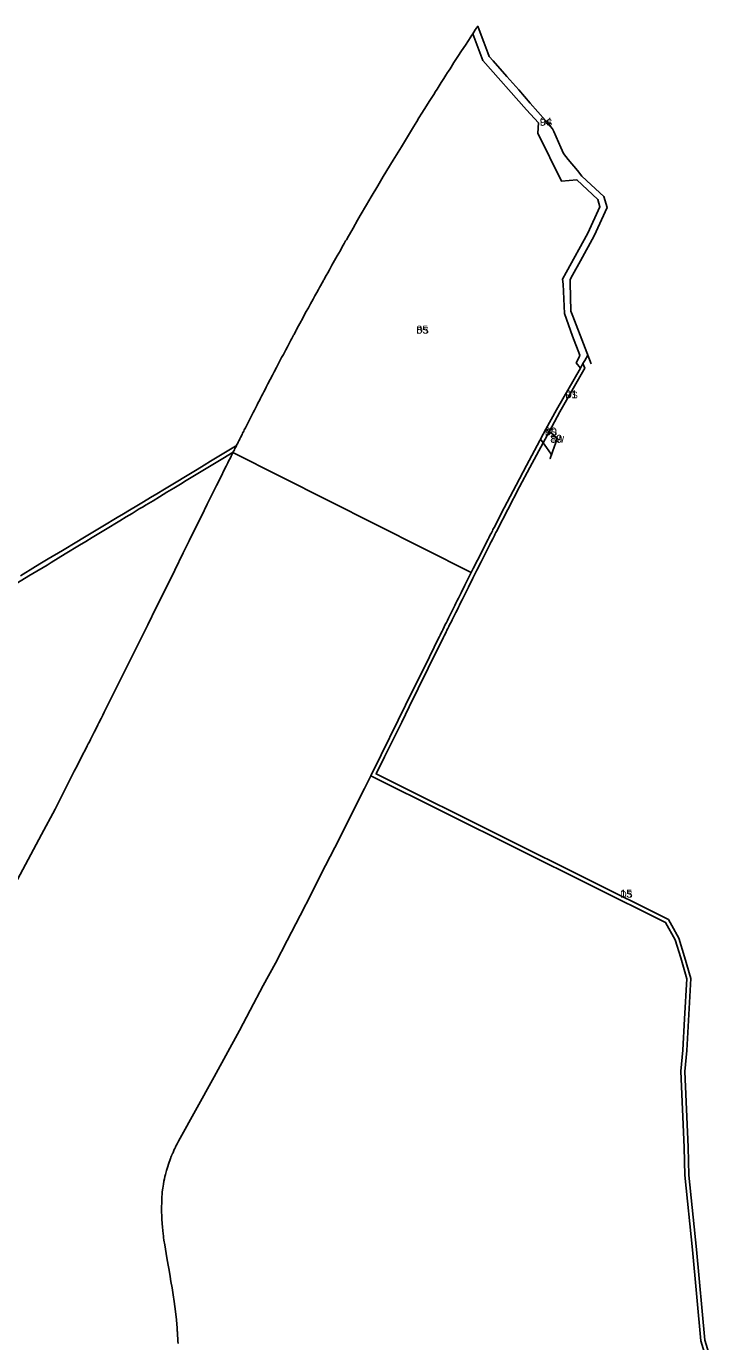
# Model space of a CAD drawing. Extents: x -537034 to -534353, y -1176562 to -1173176.
# Drawn here: x -536087 to -535575, y -1174424 to -1173438 of the extents above; entities that cross this region are included whole.
import ezdxf

# ---------------------------------------------------------------- set-up
doc = ezdxf.new("R2010")
doc.units = 0
for name, color, linetype in [('90320013', 7, 'Continuous'), ('90320023', 7, 'Continuous'), ('90390023', 7, 'Continuous'), ('ID_navrh', 7, 'Continuous')]:
    doc.layers.add(name, color=color, linetype=linetype)

msp = doc.modelspace()

# ---------------------------------------------------------------- linework, layer by layer
at = {"layer": '90320013'}
msp.add_lwpolyline([(-536091.47, -1173850.03), (-536080.14, -1173843.24), (-536075.51, -1173840.47), (-536070.52, -1173837.47), (-536059.98, -1173831.16), (-536049.21, -1173824.7), (-536044.51, -1173821.88), (-536039.74, -1173819.02), (-536029.56, -1173812.91), (-536018.83, -1173806.47), (-536014.02, -1173803.59), (-536009.62, -1173800.95), (-536004.19, -1173797.69), (-536001.59, -1173796.13), (-535999.07, -1173794.61), (-535993.92, -1173791.49), (-535989.09, -1173788.57), (-535983.49, -1173785.18), (-535978.45, -1173782.13), (-535973.46, -1173779.11), (-535968.96, -1173776.39), (-535958.98, -1173770.35), (-535953.57, -1173767.08), (-535948.96, -1173764.29), (-535930.06, -1173752.86), (-535929.43, -1173752.48), (-535929.5, -1173752.61), (-535929.75, -1173753.12), (-535930.17, -1173753.94), (-535930.58, -1173754.76), (-535930.99, -1173755.58), (-535931.4, -1173756.39), (-535931.81, -1173757.21), (-535931.97, -1173757.52), (-535939.75, -1173762.23), (-535960.88, -1173775.01), (-535967.03, -1173778.73), (-535971.51, -1173781.44), (-535976.5, -1173784.46), (-535981.54, -1173787.5), (-535987.18, -1173790.91), (-535991.99, -1173793.82), (-535997.13, -1173796.93), (-536000.01, -1173798.67), (-536002.27, -1173800.04), (-536007.72, -1173803.35), (-536012.05, -1173805.98), (-536016.81, -1173808.87), (-536027.51, -1173815.37), (-536037.66, -1173821.53), (-536042.37, -1173824.39), (-536047.04, -1173827.23), (-536057.75, -1173833.73), (-536068.28, -1173840.12), (-536071.44, -1173842.04), (-536082.06, -1173848.49), (-536085, -1173850.27), (-536124.97, -1173874.53)], dxfattribs=at)
at = {"layer": '90320023'}
for points in [[(-535663.42, -1173691.33), (-535666.09, -1173684.66), (-535668.4, -1173688.75), (-535669.68, -1173691), (-535671.6, -1173694.36), (-535674.68, -1173690.42), (-535672.65, -1173686.12), (-535672.1, -1173684.83), (-535677.54, -1173670.61), (-535683.41, -1173653.53), (-535684.54, -1173631.55), (-535685.07, -1173627.77), (-535682.21, -1173622.82), (-535666.13, -1173593.26), (-535657.03, -1173573.52), (-535658.57, -1173568.09), (-535674.26, -1173553.24), (-535685.71, -1173554.4), (-535703.6, -1173518.27), (-535703.03, -1173510.68), (-535711.9, -1173500.73), (-535744.67, -1173463.76), (-535752.34, -1173443.92), (-535751.46, -1173442.6), (-535750.38, -1173440.96), (-535749.69, -1173439.9), (-535749.4, -1173439.46), (-535749.18, -1173439.12), (-535749.05, -1173438.92), (-535748.57, -1173438.22), (-535746.8, -1173442.83), (-535744, -1173450.12), (-535740.92, -1173458.17), (-535739.9, -1173460.82), (-535737.04, -1173464.08), (-535726.71, -1173475.86), (-535717.86, -1173485.95), (-535709.19, -1173495.84), (-535697.78, -1173508.85), (-535692.41, -1173514.97), (-535691.44, -1173517.18), (-535686.26, -1173529.03), (-535684.28, -1173533.55), (-535680.66, -1173537.97), (-535673.84, -1173546.31), (-535670.41, -1173550.5), (-535663.43, -1173557.09), (-535654.08, -1173565.9), (-535651.65, -1173574.09), (-535661.19, -1173595.23), (-535671.63, -1173614.14), (-535677.56, -1173624.89), (-535679.29, -1173628.03), (-535679.23, -1173630.64), (-535678.7, -1173651.88), (-535677.33, -1173655.42), (-535668, -1173679.5)], [(-535932.12, -1173757.82), (-535931.97, -1173757.52), (-535931.81, -1173757.21), (-535931.4, -1173756.39), (-535930.99, -1173755.58), (-535930.58, -1173754.76), (-535930.17, -1173753.94), (-535929.75, -1173753.12), (-535929.5, -1173752.61), (-535929.43, -1173752.48), (-535929.34, -1173752.3), (-535928.93, -1173751.48), (-535928.52, -1173750.66), (-535928.1, -1173749.84), (-535927.69, -1173749.02), (-535927.28, -1173748.2), (-535926.87, -1173747.39), (-535926.45, -1173746.57), (-535926.04, -1173745.75), (-535925.62, -1173744.93), (-535925.21, -1173744.11), (-535924.8, -1173743.29), (-535924.38, -1173742.47), (-535923.97, -1173741.65), (-535923.55, -1173740.83), (-535923.14, -1173740.01), (-535922.72, -1173739.19), (-535921.47, -1173736.73), (-535920.64, -1173735.09), (-535919.39, -1173732.63), (-535918.13, -1173730.16), (-535916.88, -1173727.7), (-535916.04, -1173726.06), (-535915.2, -1173724.42), (-535913.94, -1173721.96), (-535913.1, -1173720.31), (-535912.25, -1173718.67), (-535911.41, -1173717.03), (-535910.56, -1173715.38), (-535909.72, -1173713.74), (-535908.87, -1173712.1), (-535908.02, -1173710.45), (-535907.17, -1173708.81), (-535905.89, -1173706.34), (-535904.19, -1173703.06), (-535902.48, -1173699.77), (-535901.19, -1173697.3), (-535899.47, -1173694.01), (-535898.61, -1173692.37), (-535897.31, -1173689.9), (-535895.58, -1173686.61), (-535894.28, -1173684.14), (-535892.54, -1173680.85), (-535891.24, -1173678.38), (-535889.92, -1173675.92), (-535888.62, -1173673.46), (-535888.61, -1173673.44), (-535888.6, -1173673.43), (-535888.59, -1173673.41), (-535888.59, -1173673.4), (-535888.58, -1173673.4), (-535888.58, -1173673.39), (-535888.58, -1173673.38), (-535888.57, -1173673.37), (-535888.56, -1173673.35), (-535888.56, -1173673.34), (-535888.55, -1173673.33), (-535888.16, -1173672.6), (-535887.91, -1173672.13), (-535887.71, -1173671.75), (-535887.43, -1173671.24), (-535887.21, -1173670.83), (-535887.04, -1173670.5), (-535886.84, -1173670.13), (-535886.68, -1173669.83), (-535886.46, -1173669.43), (-535886.31, -1173669.14), (-535885.72, -1173668.05), (-535885.31, -1173667.27), (-535884.96, -1173666.61), (-535884.64, -1173666.01), (-535884.21, -1173665.24), (-535883.86, -1173664.58), (-535881.86, -1173660.91), (-535879.78, -1173656.88), (-535877.58, -1173652.84), (-535875.5, -1173649.17), (-535874.03, -1173646.36), (-535872.01, -1173642.75), (-535870.7, -1173640.37), (-535869.29, -1173637.83), (-535868.07, -1173635.6), (-535867.21, -1173634.07), (-535866.5, -1173632.73), (-535865.29, -1173630.57), (-535864.82, -1173629.72), (-535864.19, -1173628.6), (-535863.82, -1173627.94), (-535863.5, -1173627.33), (-535862.2, -1173625.07), (-535861.04, -1173622.93), (-535859.76, -1173620.67), (-535857.86, -1173617.18), (-535855.84, -1173613.7), (-535854.01, -1173610.34), (-535851.56, -1173606.18), (-535850.1, -1173603.55), (-535848.69, -1173601.04), (-535847.65, -1173599.15), (-535847.04, -1173598.17), (-535845.5, -1173595.47), (-535844.79, -1173594.23), (-535842.03, -1173589.46), (-535838.73, -1173583.65), (-535836.59, -1173579.98), (-535832.07, -1173572.1), (-535828.4, -1173565.98), (-535823.51, -1173557.91), (-535819.48, -1173550.82), (-535812.02, -1173538.6), (-535805.78, -1173528.45), (-535796.72, -1173513.55), (-535795.59, -1173511.7), (-535794.26, -1173509.57), (-535792.64, -1173506.93), (-535790.41, -1173503.44), (-535788.7, -1173500.63), (-535787.04, -1173497.94), (-535784.97, -1173494.7), (-535783.04, -1173491.61), (-535781.54, -1173489.23), (-535780.2, -1173487.12), (-535779.1, -1173485.35), (-535775.95, -1173480.36), (-535773.9, -1173477.22), (-535772.4, -1173474.86), (-535771.12, -1173472.81), (-535770.58, -1173471.97), (-535769.29, -1173469.99), (-535768.51, -1173468.76), (-535767.41, -1173467.11), (-535766.37, -1173465.46), (-535763.47, -1173460.97), (-535760.66, -1173456.57), (-535757.85, -1173452.35), (-535755.58, -1173448.83), (-535753.05, -1173444.98), (-535752.34, -1173443.92), (-535744.67, -1173463.76), (-535711.9, -1173500.73), (-535703.03, -1173510.68), (-535703.6, -1173518.27), (-535685.71, -1173554.4), (-535674.26, -1173553.24), (-535658.57, -1173568.09), (-535657.03, -1173573.52), (-535666.13, -1173593.26), (-535682.21, -1173622.82), (-535685.07, -1173627.77), (-535684.54, -1173631.55), (-535683.41, -1173653.53), (-535677.54, -1173670.61), (-535672.1, -1173684.83), (-535672.65, -1173686.12), (-535674.68, -1173690.42), (-535671.6, -1173694.36), (-535689.54, -1173725.83), (-535697.41, -1173740.24), (-535701.53, -1173747.78), (-535702.04, -1173748.72), (-535712.13, -1173767.54), (-535719.86, -1173782.15), (-535728.74, -1173799.17), (-535736.36, -1173813.97), (-535736.76, -1173814.75), (-535737.16, -1173815.53), (-535737.56, -1173816.31), (-535738.36, -1173817.87), (-535738.76, -1173818.66), (-535739.16, -1173819.44), (-535739.55, -1173820.22), (-535739.95, -1173821.01), (-535740.35, -1173821.79), (-535740.75, -1173822.57), (-535741.15, -1173823.36), (-535741.55, -1173824.14), (-535741.95, -1173824.92), (-535742.35, -1173825.71), (-535748.71, -1173838.29), (-535751.89, -1173844.6), (-535753.49, -1173847.78)], [(-535697.41, -1173740.24), (-535689.54, -1173725.83), (-535671.6, -1173694.36), (-535669.68, -1173691), (-535668.29, -1173694.6), (-535668.99, -1173695.85), (-535686.92, -1173727.29), (-535695.05, -1173742.16)], [(-535699.59, -1173750.49), (-535701.53, -1173747.78), (-535697.41, -1173740.24), (-535695.05, -1173742.16)]]:
    msp.add_lwpolyline(points, close=True, dxfattribs=at)
for points in [[(-535577.9, -1174434.99), (-535581.3, -1174423.66), (-535587.52, -1174355.45), (-535593.35, -1174299.53), (-535593.7, -1174278.64), (-535596.28, -1174221.57), (-535594.79, -1174205.64), (-535593.45, -1174182.15), (-535591.76, -1174152.32), (-535596.36, -1174136.54), (-535600.68, -1174123.06), (-535607.79, -1174109.96), (-535828.81, -1174000.01), (-535821.06, -1173984.4), (-535808.24, -1173958.45), (-535802.65, -1173947.12), (-535795.88, -1173933.37), (-535788.33, -1173918.03), (-535777.63, -1173896.33), (-535777.23, -1173895.52), (-535776.83, -1173894.72), (-535776.44, -1173893.92), (-535776.04, -1173893.12), (-535775.65, -1173892.32), (-535775.25, -1173891.52), (-535774.86, -1173890.72), (-535774.46, -1173889.92), (-535774.06, -1173889.12), (-535773.67, -1173888.32), (-535772.88, -1173886.72), (-535772.09, -1173885.12), (-535771.29, -1173883.52), (-535770.5, -1173881.92), (-535769.71, -1173880.33), (-535768.53, -1173877.93), (-535767.73, -1173876.34), (-535766.55, -1173873.95), (-535765.76, -1173872.35), (-535764.96, -1173870.76), (-535764.17, -1173869.17), (-535762.99, -1173866.78), (-535761.01, -1173862.81), (-535758.23, -1173857.25), (-535754.67, -1173850.13), (-535753.49, -1173847.78), (-535751.89, -1173844.6), (-535748.71, -1173838.29), (-535742.35, -1173825.71), (-535741.95, -1173824.92), (-535741.55, -1173824.14), (-535741.15, -1173823.36), (-535740.75, -1173822.57), (-535740.35, -1173821.79), (-535739.95, -1173821.01), (-535739.55, -1173820.22), (-535739.16, -1173819.44), (-535738.76, -1173818.66), (-535738.36, -1173817.87), (-535737.56, -1173816.31), (-535737.16, -1173815.53), (-535736.76, -1173814.75), (-535736.36, -1173813.97), (-535728.74, -1173799.17), (-535719.86, -1173782.15), (-535712.13, -1173767.54), (-535702.04, -1173748.72), (-535701.53, -1173747.78), (-535699.59, -1173750.49), (-535709.48, -1173768.95), (-535717.2, -1173783.55), (-535726.08, -1173800.55), (-535733.69, -1173815.34), (-535734.09, -1173816.12), (-535734.49, -1173816.9), (-535734.89, -1173817.68), (-535735.68, -1173819.24), (-535736.08, -1173820.02), (-535736.48, -1173820.8), (-535737.28, -1173822.37), (-535737.68, -1173823.15), (-535738.08, -1173823.93), (-535738.48, -1173824.72), (-535738.88, -1173825.5), (-535739.27, -1173826.28), (-535739.67, -1173827.06), (-535746.04, -1173839.64), (-535749.21, -1173845.94), (-535752.16, -1173851.81), (-535755.55, -1173858.6), (-535758.32, -1173864.15), (-535760.3, -1173868.12), (-535761.49, -1173870.5), (-535762.28, -1173872.1), (-535763.07, -1173873.69), (-535763.86, -1173875.28), (-535765.05, -1173877.67), (-535765.84, -1173879.26), (-535767.02, -1173881.66), (-535767.81, -1173883.25), (-535768.61, -1173884.85), (-535769.4, -1173886.45), (-535770.19, -1173888.05), (-535770.98, -1173889.65), (-535771.37, -1173890.45), (-535771.77, -1173891.25), (-535772.17, -1173892.05), (-535772.56, -1173892.85), (-535772.96, -1173893.65), (-535773.35, -1173894.45), (-535773.75, -1173895.25), (-535774.14, -1173896.05), (-535774.54, -1173896.85), (-535774.94, -1173897.65), (-535785.64, -1173919.36), (-535793.19, -1173934.7), (-535799.96, -1173948.44), (-535805.55, -1173959.78), (-535818.37, -1173985.73), (-535824.79, -1173998.66), (-535824.34, -1173998.89), (-535728.12, -1174046.76), (-535605.58, -1174107.71), (-535603.1, -1174112.3), (-535597.91, -1174121.88), (-535593.49, -1174135.66), (-535588.73, -1174151.97), (-535591.8, -1174205.87), (-535593.27, -1174221.64), (-535590.7, -1174278.54), (-535590.36, -1174299.35), (-535584.54, -1174355.16), (-535578.34, -1174423.09), (-535575.43, -1174432.79)], [(-536093.59, -1174077.8), (-536075.49, -1174044.05), (-536065.47, -1174024.98), (-536050.99, -1173996.56), (-536048.98, -1173992.62), (-536047.77, -1173990.26), (-536046.16, -1173987.11), (-536044.55, -1173983.96), (-536042.95, -1173980.8), (-536041.34, -1173977.64), (-536040.54, -1173976.06), (-536039.74, -1173974.48), (-536038.93, -1173972.9), (-536038.13, -1173971.32), (-536037.33, -1173969.74), (-536036.13, -1173967.36), (-536034.93, -1173964.99), (-536033.33, -1173961.82), (-536032.53, -1173960.23), (-536030.93, -1173957.06), (-536029.73, -1173954.68), (-536028.54, -1173952.3), (-536023.35, -1173941.97), (-536016.58, -1173928.44), (-536009.83, -1173914.87), (-536003.87, -1173902.88), (-535995.94, -1173886.85), (-535989.59, -1173874), (-535983.24, -1173861.13), (-535975.7, -1173845.81), (-535969.34, -1173832.9), (-535964.95, -1173824), (-535960.56, -1173815.08), (-535955.75, -1173805.34), (-535951.33, -1173796.4), (-535946.89, -1173787.44), (-535944.47, -1173782.56), (-535942.03, -1173777.65), (-535937.55, -1173768.66), (-535937.25, -1173768.07), (-535937.15, -1173767.87), (-535936.73, -1173767.03), (-535935.91, -1173765.39), (-535935.09, -1173763.76), (-535934.27, -1173762.12), (-535933.45, -1173760.49), (-535932.63, -1173758.85), (-535932.12, -1173757.82), (-535753.49, -1173847.78), (-535754.67, -1173850.13), (-535758.23, -1173857.25), (-535761.01, -1173862.81), (-535762.99, -1173866.78), (-535764.17, -1173869.17), (-535764.96, -1173870.76), (-535765.76, -1173872.35), (-535766.55, -1173873.95), (-535767.73, -1173876.34), (-535768.53, -1173877.93), (-535769.71, -1173880.33), (-535770.5, -1173881.92), (-535771.29, -1173883.52), (-535772.09, -1173885.12), (-535772.88, -1173886.72), (-535773.67, -1173888.32), (-535774.06, -1173889.12), (-535774.46, -1173889.92), (-535774.86, -1173890.72), (-535775.25, -1173891.52), (-535775.65, -1173892.32), (-535776.04, -1173893.12), (-535776.44, -1173893.92), (-535776.83, -1173894.72), (-535777.23, -1173895.52), (-535777.63, -1173896.33), (-535788.33, -1173918.03), (-535795.88, -1173933.37), (-535802.65, -1173947.12), (-535808.24, -1173958.45), (-535821.06, -1173984.4), (-535828.81, -1174000.01), (-535833.57, -1174009.59), (-535841.68, -1174025.86), (-535852.31, -1174047.03), (-535862.61, -1174067.4), (-535872.17, -1174086.14), (-535873, -1174087.77), (-535881.74, -1174104.71), (-535891.53, -1174123.6), (-535900.28, -1174140.39), (-535909.37, -1174157.17), (-535919.16, -1174175.71), (-535927.21, -1174191.1), (-535946.09, -1174225.72), (-535972.84, -1174273.97), (-535973.9, -1174275.96), (-535974.53, -1174277.12), (-535974.84, -1174277.72), (-535975.24, -1174278.53), (-535975.67, -1174279.4), (-535976.07, -1174280.25), (-535976.35, -1174280.83), (-535976.73, -1174281.67), (-535977.01, -1174282.31), (-535977.27, -1174282.88), (-535977.37, -1174283.13), (-535977.48, -1174283.36), (-535977.5, -1174283.43), (-535977.53, -1174283.5), (-535977.56, -1174283.56), (-535977.58, -1174283.62), (-535977.6, -1174283.66), (-535977.63, -1174283.72), (-535977.66, -1174283.79), (-535977.69, -1174283.87), (-535977.72, -1174283.93), (-535977.73, -1174283.97), (-535977.81, -1174284.14), (-535977.89, -1174284.34), (-535977.93, -1174284.44), (-535978.03, -1174284.68), (-535978.16, -1174284.98), (-535978.26, -1174285.23), (-535978.35, -1174285.47), (-535978.58, -1174286.03), (-535978.72, -1174286.4), (-535978.97, -1174287.02), (-535979.24, -1174287.74), (-535979.46, -1174288.39), (-535979.94, -1174289.65), (-535980.49, -1174291.25), (-535981.01, -1174292.89), (-535981.47, -1174294.4), (-535981.93, -1174295.97), (-535982.21, -1174297.02), (-535982.72, -1174298.92), (-535983.04, -1174300.36), (-535983.44, -1174302.16), (-535983.81, -1174304.02), (-535984.18, -1174306.05), (-535984.66, -1174309.2), (-535985.05, -1174312.04), (-535985.49, -1174317.46), (-535985.58, -1174326.03), (-535985.4, -1174330.79), (-535985.37, -1174332.48), (-535985.21, -1174335.55), (-535984.98, -1174338.43), (-535984.73, -1174340.89), (-535984.44, -1174343.35), (-535984.24, -1174344.91), (-535984.07, -1174346.15), (-535983.79, -1174348.09), (-535983.24, -1174351.73), (-535982.73, -1174354.88), (-535982.18, -1174358.19), (-535981.62, -1174361.4), (-535980.68, -1174366.79), (-535979.99, -1174370.69), (-535979.16, -1174375.44), (-535978.54, -1174379.1), (-535977.73, -1174383.96), (-535976.93, -1174389.07), (-535976.21, -1174394.02), (-535975.23, -1174401.58), (-535974.52, -1174407.91), (-535973.96, -1174414.06), (-535973.93, -1174414.51), (-535973.89, -1174414.96), (-535973.85, -1174415.41), (-535973.82, -1174415.87), (-535973.79, -1174416.32), (-535973.75, -1174416.78), (-535973.72, -1174417.23), (-535973.63, -1174418.61), (-535973.57, -1174419.54), (-535973.43, -1174421.87), (-535973.34, -1174423.76), (-535973.25, -1174425.67)]]:
    msp.add_lwpolyline(points, dxfattribs=at)
at = {"layer": '90390023'}
msp.add_lwpolyline([(-535699.59, -1173750.49), (-535695.05, -1173742.16), (-535694.65, -1173742.49), (-535692.64, -1173743.73), (-535689.01, -1173747.62), (-535688.76, -1173747.02), (-535690.95, -1173752.98), (-535694.35, -1173762.25), (-535693.31, -1173759.31), (-535693.54, -1173758.96), (-535697.05, -1173754.05)], close=True, dxfattribs=at)

# ---------------------------------------------------------------- texts
at = {"layer": '90320023'}
for rotation, p in [(0, (-535702, -1173512.78)), (0, (-535794.58, -1173668.58)), (360, (-535682.85, -1173717.12)), (360, (-535698.29, -1173744.98)), (0, (-535641.77, -1174091.39))]:
    msp.add_text('DS', height=5, rotation=rotation, dxfattribs=at).set_placement(p)
at = {"layer": '90390023'}
msp.add_text('TW', height=5, rotation=360, dxfattribs=at).set_placement((-535694.17, -1173750.43))
at = {"layer": 'ID_navrh'}
for s, rotation, p in [('94', 0, (-535702, -1173512.78)), ('85', 360, (-535794.58, -1173668.58)), ('91', 360, (-535682.85, -1173717.12)), ('90', 360, (-535698.29, -1173744.98)), ('89', 360, (-535694.17, -1173750.43)), ('15', 0, (-535641.77, -1174091.39))]:
    msp.add_text(s, height=6, rotation=rotation, dxfattribs=at).set_placement(p)

doc.saveas('drawing.dxf')
